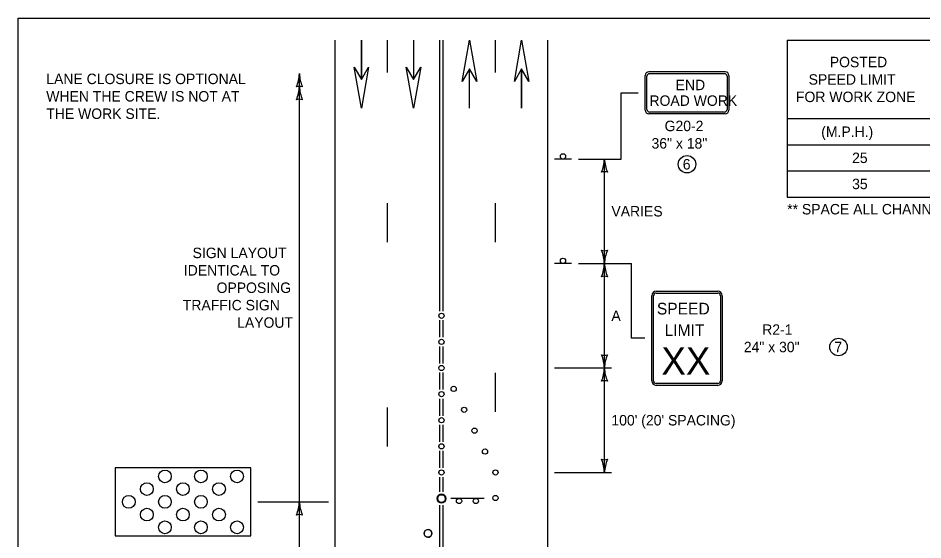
# Model space of a CAD drawing. Extents: x 49991.4 to 50021, y 49987.6 to 50011.4.
# Drawn here: x 49999.38 to 50004.58, y 49996 to 49999 of the extents above; entities that cross this region are included whole.
import ezdxf

# ---------------------------------------------------------------- set-up
doc = ezdxf.new("R2010")
doc.units = 0
for name, color, linetype in [('Level 1', 7, 'Continuous'), ('Level 2', 7, 'Continuous'), ('Level 3', 7, 'Continuous')]:
    doc.layers.add(name, color=color, linetype=linetype)

msp = doc.modelspace()

# ---------------------------------------------------------------- linework, layer by layer
at = {"layer": 'Level 1'}
for p, q in [((50001.2058, 49993.024), (50001.2058, 49998.8719)), ((50001.355, 49998.8719), (50001.355, 49998.646)), ((50001.3554, 49998.8719), (50001.3554, 49998.646)), ((50001.5059, 49998.686), (50001.5059, 49998.8719)), ((50001.655, 49998.8719), (50001.655, 49998.646)), ((50001.6554, 49998.8719), (50001.6554, 49998.646)), ((50001.8058, 49997.3163), (50001.8058, 49998.8719)), ((50001.8258, 49997.3163), (50001.8258, 49998.8719)), ((50002.1259, 49998.686), (50002.1259, 49998.8719)), ((50002.4258, 49995.0313), (50002.4258, 49998.8719)), ((50001.9758, 49998.4818), (50001.9758, 49998.7077)), ((50001.9762, 49998.4818), (50001.9762, 49998.7077)), ((50002.2762, 49998.4818), (50002.2762, 49998.7077)), ((50002.2766, 49998.4818), (50002.2766, 49998.7077)), ((50002.9862, 49998.47), (50002.9862, 49998.67)), ((50003.4462, 49998.69), (50003.0062, 49998.69)), ((50003.4412, 49998.68), (50003.0112, 49998.68)), ((50003.4662, 49998.67), (50003.4662, 49998.47)), ((50002.9962, 49998.475), (50002.9962, 49998.665)), ((50003.4562, 49998.665), (50003.4562, 49998.475)), ((50003.4412, 49998.46), (50003.0112, 49998.46)), ((50003.4461, 49998.45), (50003.0061, 49998.45)), ((50002.5618, 49998.1901), (50002.4658, 49998.1901)), ((50001.5059, 49997.712), (50001.5059, 49997.936)), ((50002.1259, 49997.712), (50002.1259, 49997.936)), ((50002.5618, 49997.5901), (50002.4658, 49997.5901)), ((50003.0488, 49997.4307), (50003.4033, 49997.4307)), ((50003.0488, 49997.4201), (50003.4033, 49997.4201)), ((50003.226, 49997.4307), (50003.226, 49997.4307)), ((50003.0235, 49996.9158), (50003.0235, 49997.4053)), ((50003.034, 49996.9158), (50003.034, 49997.4053)), ((50003.418, 49997.4053), (50003.418, 49996.9158)), ((50003.4286, 49997.4053), (50003.4286, 49996.9158)), ((50001.8055, 49997.1663), (50001.8055, 49997.2639)), ((50001.8255, 49997.1663), (50001.8255, 49997.2639)), ((50001.8055, 49997.0163), (50001.8055, 49997.1139)), ((50001.8255, 49997.0163), (50001.8255, 49997.1139)), ((50001.8055, 49996.8663), (50001.8055, 49996.9639)), ((50001.8255, 49996.8663), (50001.8255, 49996.9639)), ((50002.1259, 49996.738), (50002.1259, 49996.962)), ((50003.4033, 49996.9011), (50003.0488, 49996.9011)), ((50003.4033, 49996.8905), (50003.0488, 49996.8905)), ((50001.8055, 49996.7163), (50001.8055, 49996.8139)), ((50001.8255, 49996.7163), (50001.8255, 49996.8139)), ((50001.5059, 49996.5391), (50001.5059, 49996.7631)), ((50001.8055, 49996.5663), (50001.8055, 49996.6639)), ((50001.8255, 49996.5663), (50001.8255, 49996.6639)), ((50001.8055, 49996.4163), (50001.8055, 49996.514)), ((50001.8255, 49996.4163), (50001.8255, 49996.514)), ((50001.8055, 49996.2781), (50001.8055, 49996.364)), ((50001.8255, 49996.2781), (50001.8255, 49996.364)), ((50001.9648, 49996.2415), (50001.8688, 49996.2415)), ((50002.0608, 49996.2415), (50001.9648, 49996.2415)), ((50001.8058, 49995.4153), (50001.8058, 49996.2021)), ((50001.8258, 49995.4153), (50001.8258, 49996.2021))]:
    msp.add_line(p, q, dxfattribs=at)
for points in [[(49999.3835, 49998.9992), (50016.7501, 49998.9992), (50016.7501, 49987.7988), (49999.3835, 49987.7988)], [(50001.9342, 49998.6354), (50001.9758, 49998.8719), (50002.0178, 49998.6354), (50001.9758, 49998.7076)], [(50002.2346, 49998.6354), (50002.2762, 49998.8719), (50002.3182, 49998.6354), (50002.2762, 49998.7076)], [(50001.397, 49998.7183), (50001.3554, 49998.4818), (50001.3134, 49998.7183), (50001.3554, 49998.6461)], [(50001.697, 49998.7183), (50001.6554, 49998.4818), (50001.6134, 49998.7183), (50001.6554, 49998.6461)], [(49999.9406, 49996.0267), (50000.7203, 49996.0267), (50000.7203, 49996.4167), (49999.9406, 49996.4167)], [(49999.9406, 49996.0267), (50000.7203, 49996.0267), (50000.7203, 49996.4167), (49999.9406, 49996.4167)]]:
    msp.add_lwpolyline(points, close=True, dxfattribs=at)
for centre, radius in [((50002.5137, 49998.2053), 0.0152), ((50002.5137, 49997.6053), 0.0152), ((50001.8155, 49997.2901), 0.015), ((50001.8155, 49997.1401), 0.015), ((50001.8155, 49996.9901), 0.015), ((50001.8155, 49996.8401), 0.015), ((50001.8857, 49996.8701), 0.015), ((50001.9457, 49996.7501), 0.015), ((50001.8155, 49996.6901), 0.015), ((50002.0057, 49996.6301), 0.015), ((50001.8155, 49996.5401), 0.015), ((50002.0657, 49996.5101), 0.015), ((50000.2268, 49996.3677), 0.0366), ((50000.2268, 49996.3677), 0.0366), ((50000.4339, 49996.3677), 0.0366), ((50000.4339, 49996.3677), 0.0366), ((50000.641, 49996.3677), 0.0366), ((50000.641, 49996.3677), 0.0366), ((50001.8155, 49996.3901), 0.015), ((50002.1256, 49996.3901), 0.015), ((50000.1232, 49996.2946), 0.0366), ((50000.1232, 49996.2946), 0.0366), ((50000.3303, 49996.2946), 0.0366), ((50000.3303, 49996.2946), 0.0366), ((50000.5374, 49996.2946), 0.0366), ((50000.5374, 49996.2946), 0.0366), ((50000.0196, 49996.2215), 0.0366), ((50000.0196, 49996.2215), 0.0366), ((50000.2268, 49996.2215), 0.0366), ((50000.2268, 49996.2215), 0.0366), ((50000.4339, 49996.2215), 0.0366), ((50000.4339, 49996.2215), 0.0366), ((50001.8158, 49996.2401), 0.025), ((50001.8158, 49996.2401), 0.0225), ((50001.8158, 49996.2401), 0.0225), ((50001.9168, 49996.2263), 0.0152), ((50002.0128, 49996.2263), 0.0152), ((50002.1258, 49996.2435), 0.015), ((50000.1232, 49996.1484), 0.0366), ((50000.1232, 49996.1484), 0.0366), ((50000.3303, 49996.1484), 0.0366), ((50000.3303, 49996.1484), 0.0366), ((50000.5374, 49996.1484), 0.0366), ((50000.5374, 49996.1484), 0.0366), ((50000.2268, 49996.0753), 0.0366), ((50000.2268, 49996.0753), 0.0366), ((50000.4339, 49996.0753), 0.0366), ((50000.4339, 49996.0753), 0.0366), ((50000.641, 49996.0753), 0.0366), ((50000.641, 49996.0753), 0.0366), ((50001.7383, 49996.0405), 0.0225)]:
    msp.add_circle(centre, radius, dxfattribs=at)
for centre, radius, start, end in [((50003.0062, 49998.67), 0.02, 90, 180), ((50003.0112, 49998.665), 0.015, 90, 180), ((50003.4412, 49998.665), 0.015, 360, 90), ((50003.4462, 49998.67), 0.02, 360, 90), ((50003.0061, 49998.47), 0.02, 180, 270), ((50003.0112, 49998.475), 0.015, 180, 270), ((50003.4412, 49998.475), 0.015, 270, 360), ((50003.4461, 49998.47), 0.02, 270, 360), ((50003.0488, 49997.4053), 0.0253, 90, 180), ((50003.0488, 49997.4053), 0.0148, 90, 180), ((50003.4033, 49997.4053), 0.0253, 360, 90), ((50003.4033, 49997.4053), 0.0148, 360, 90), ((50003.0488, 49996.9158), 0.0253, 180, 270), ((50003.0488, 49996.9158), 0.0148, 180, 270), ((50003.4033, 49996.9158), 0.0148, 270, 360), ((50003.4033, 49996.9158), 0.0253, 270, 360), ((50001.8158, 49996.2401), 0.025, 0, 180), ((50001.8158, 49996.2401), 0.025, 180, 0), ((50001.8158, 49996.2401), 0.0225, 356.6361, 176.6361), ((50001.8158, 49996.2401), 0.0225, 176.6361, 356.6361), ((50001.7383, 49996.0405), 0.0225, 356.6361, 176.6361), ((50001.7383, 49996.0405), 0.0225, 176.6361, 356.6361)]:
    msp.add_arc(centre, radius, start, end, dxfattribs=at)
at = {"layer": 'Level 2'}
for p, q in [((50003.8015, 49998.8719), (50007.7315, 49998.8719)), ((50003.8015, 49998.8719), (50003.8015, 49997.9719)), ((50003.8015, 49998.4219), (50007.7315, 49998.4219)), ((50003.8015, 49998.2719), (50007.7315, 49998.2719)), ((50003.8015, 49998.1219), (50007.7315, 49998.1219)), ((50003.8015, 49997.9719), (50007.7315, 49997.9719))]:
    msp.add_line(p, q, dxfattribs=at)
for centre in [(50003.2261, 49998.1599), (50004.0965, 49997.1106)]:
    msp.add_circle(centre, 0.0501, dxfattribs=at)
at = {"layer": 'Level 3'}
for p, q in [((50000.9994, 49996.2217), (50000.9994, 49998.6802)), ((50002.8483, 49998.1901), (50002.8483, 49998.57)), ((50002.8483, 49998.57), (50002.9462, 49998.57)), ((50002.6018, 49998.1901), (50002.8483, 49998.1901)), ((50002.7518, 49997.5901), (50002.7518, 49998.1901)), ((50002.6018, 49997.5901), (50002.9063, 49997.5901)), ((50002.7518, 49996.9901), (50002.7518, 49997.5901)), ((50002.9835, 49997.1606), (50002.9062, 49997.1606)), ((50002.4658, 49996.9901), (50002.7918, 49996.9901)), ((50002.7518, 49996.3901), (50002.7518, 49996.9901)), ((50002.4658, 49996.3901), (50002.7918, 49996.3901)), ((50000.7603, 49996.2217), (50001.1658, 49996.2217)), ((50000.9994, 49995.4217), (50000.9994, 49996.2217))]:
    msp.add_line(p, q, dxfattribs=at)
msp.add_lwpolyline([(50002.9062, 49997.5901), (50002.9062, 49997.1606)], dxfattribs=at)
for centre, radius, start, end in [((50000.7772, 49998.6894), 0.2223, 337.456, 357.6395), ((50001.2321, 49998.6917), 0.233, 182.8273, 202.0772), ((50000.9994, 49998.552), 0.0548, 72.1388, 107.8612), ((50000.7772, 49998.616), 0.2223, 337.456, 357.6395), ((50001.2321, 49998.6183), 0.233, 182.8273, 202.0772), ((50000.9994, 49998.4786), 0.0548, 72.1388, 107.8612), ((50002.5296, 49998.1993), 0.2223, 337.456, 357.6395), ((50002.9845, 49998.2016), 0.233, 182.8273, 202.0772), ((50002.7518, 49998.0619), 0.0548, 72.1388, 107.8612), ((50002.7518, 49997.7184), 0.0548, 252.1388, 287.8612), ((50002.5191, 49997.5787), 0.233, 2.8273, 22.0772), ((50002.9739, 49997.581), 0.2223, 157.456, 177.6395), ((50002.5296, 49997.5993), 0.2223, 337.456, 357.6395), ((50002.9845, 49997.6016), 0.233, 182.8273, 202.0772), ((50002.7518, 49997.4619), 0.0548, 72.1388, 107.8612), ((50002.7518, 49997.1184), 0.0548, 252.1388, 287.8612), ((50002.5191, 49996.9787), 0.233, 2.8273, 22.0772), ((50002.9739, 49996.981), 0.2223, 157.456, 177.6395), ((50002.5191, 49997.0016), 0.233, 337.9228, 357.1727), ((50002.9739, 49996.9993), 0.2223, 182.3605, 202.544), ((50002.7518, 49996.8619), 0.0548, 72.1388, 107.8612), ((50002.5296, 49996.381), 0.2223, 2.3605, 22.544), ((50002.7518, 49996.5184), 0.0548, 252.1388, 287.8612), ((50002.9845, 49996.3787), 0.233, 157.9228, 177.1727), ((50000.7772, 49996.2309), 0.2223, 337.456, 357.6395), ((50001.2321, 49996.2332), 0.233, 182.8273, 202.0772), ((50000.9994, 49996.0935), 0.0548, 72.1388, 107.8612)]:
    msp.add_arc(centre, radius, start, end, dxfattribs=at)

# ---------------------------------------------------------------- texts
at = {"layer": 'Level 1'}
for s, height, p in [('END', 0.06, (50003.161, 49998.5854)), ('ROAD WORK', 0.06, (50003.0104, 49998.4954)), ('SPEED', 0.06695, (50003.0529, 49997.2974)), ('LIMIT', 0.06695, (50003.0972, 49997.1736)), ('XX', 0.15773, (50003.0789, 49996.9516))]:
    msp.add_text(s, height=height, rotation=360, dxfattribs=at).set_placement(p)
at = {"layer": 'Level 2'}
for s, p in [('POSTED', (50004.0462, 49998.7169)), ('LANE CLOSURE IS OPTIONAL', (49999.5454, 49998.6202)), ('SPEED LIMIT', (50003.9249, 49998.6169)), ('WHEN THE CREW IS NOT AT', (49999.5454, 49998.5202)), ('FOR WORK ZONE', (50003.8519, 49998.5169)), ('THE WORK SITE.', (49999.5454, 49998.4202)), ('(M.P.H.)', (50003.9971, 49998.3169)), ('25', (50004.1745, 49998.1669)), ('35', (50004.1746, 49998.0169)), ('VARIES', (50002.7918, 49997.8601)), ('** SPACE ALL CHANNELIZING DEVICES AT "G" UNLESS OTHERWISE NOTED.', (50003.8015, 49997.8719)), ('SIGN LAYOUT', (50000.3859, 49997.621)), ('IDENTICAL TO', (50000.3356, 49997.521)), ('OPPOSING', (50000.5237, 49997.421)), ('TRAFFIC SIGN', (50000.3298, 49997.321)), ('A', (50002.7918, 49997.2601)), ('LAYOUT', (50000.6419, 49997.221)), ('R2-1', (50003.658, 49997.1806)), ('24" x 30"', (50003.5524, 49997.0806))]:
    msp.add_text(s, height=0.06, dxfattribs=at).set_placement(p)
for s, p in [('G20-2', (50003.0975, 49998.35)), ('36" x 18"', (50003.0223, 49998.25)), ('6', (50003.2016, 49998.1299)), ('7', (50004.0727, 49997.0806)), ("100' (20' SPACING)", (50002.7918, 49996.6601))]:
    msp.add_text(s, height=0.06, rotation=360, dxfattribs=at).set_placement(p)

doc.saveas('drawing.dxf')
